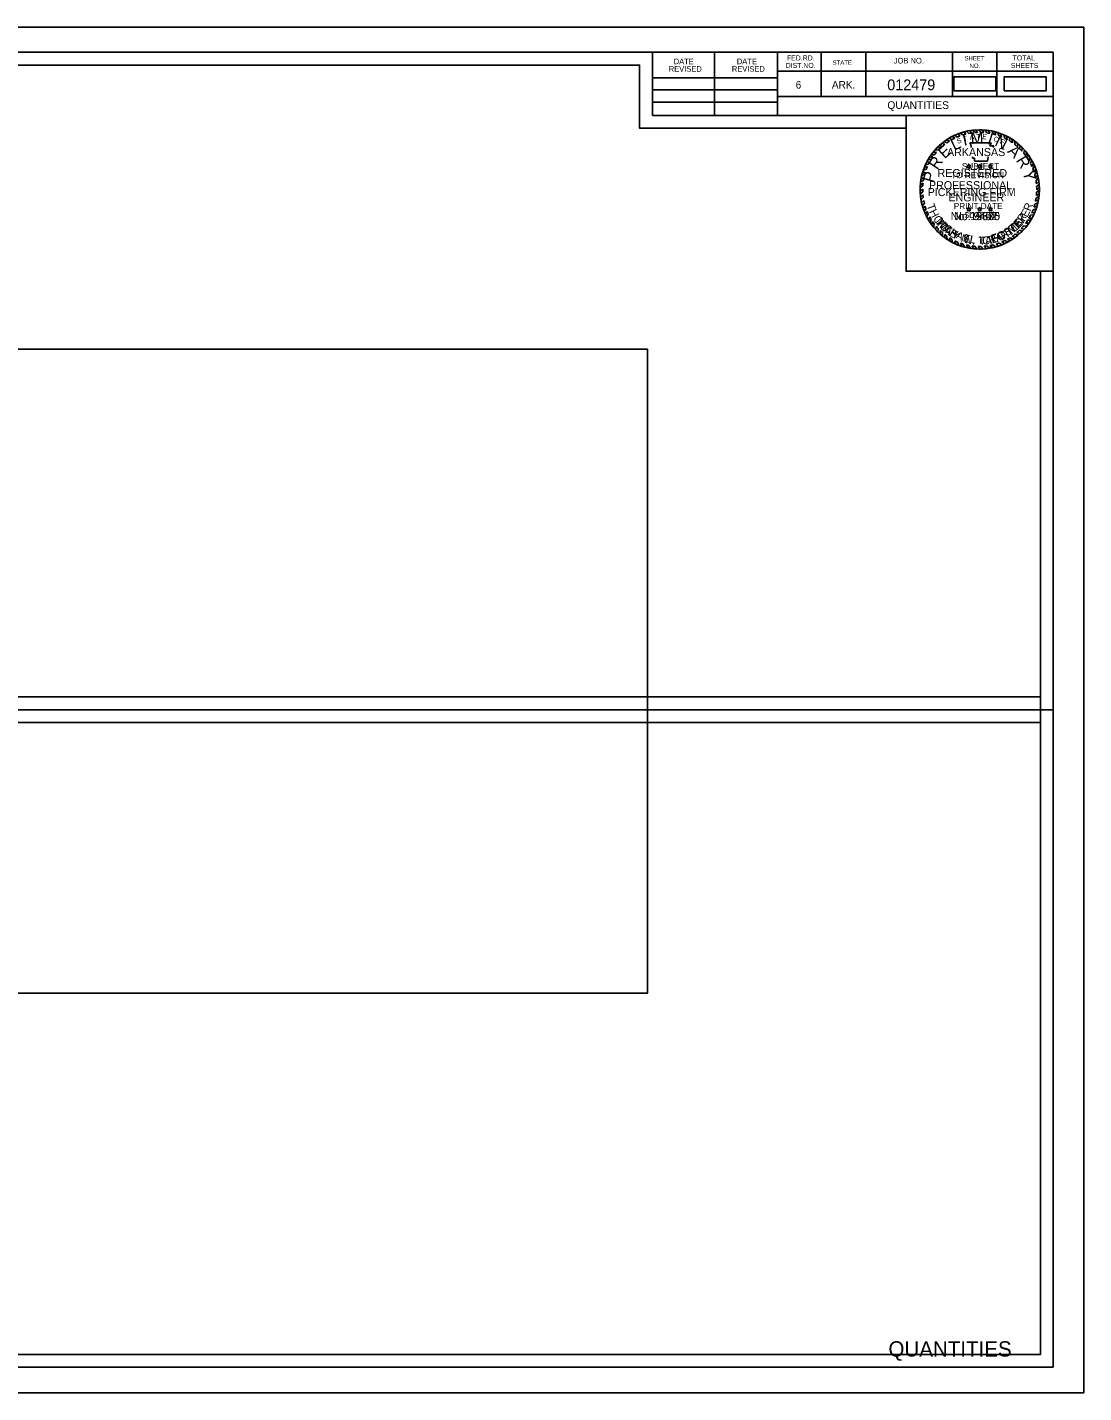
# Model space of a CAD drawing. Extents: x 1369290 to 1371547, y 379683 to 379897.
# Drawn here: x 1369458.1 to 1369623.1, y 379683.5 to 379896.8 of the extents above; entities that cross this region are included whole.
import ezdxf

# ---------------------------------------------------------------- set-up
doc = ezdxf.new("R2010")
doc.units = 0
for name, color, linetype in [('Default', 7, 'Continuous'), ('R_Border', 7, 'Continuous'), ('R_Border Notes', 7, 'Continuous'), ('R_Border Plan-Plan', 7, 'Continuous'), ('R_Border Title', 7, 'Continuous'), ('R_No Plot', 7, 'Continuous'), ('STAMP_PE_CRAFTON', 7, 'Continuous'), ('STAMP_PE_FOSTER', 7, 'Continuous'), ('STAMP_PE_SEAL-INFO', 7, 'Continuous'), ('STAMP_PE_TAEGTMEYER', 7, 'Continuous'), ('STAMP_PE_TXT', 7, 'Continuous'), ('STAMP_PRELIMINARY', 7, 'Continuous')]:
    doc.layers.add(name, color=color, linetype=linetype)

msp = doc.modelspace()

# ---------------------------------------------------------------- linework, layer by layer
at = {"layer": 'Default'}
for points in [[(1369602.84, 379886.89), (1369609.41, 379886.89), (1369609.41, 379889.08), (1369602.84, 379889.08)], [(1369610.71, 379886.89), (1369617.28, 379886.89), (1369617.28, 379889.08), (1369610.71, 379889.08)], [(1369360.05, 379745.89), (1369554.97, 379745.89), (1369554.97, 379846.52), (1369360.05, 379846.52)]]:
    msp.add_lwpolyline(points, close=True, dxfattribs=at)
at = {"layer": 'R_Border'}
for p, q in [((1369302.22, 379892.93), (1369618.4, 379892.93)), ((1369555.76, 379883.05), (1369555.76, 379892.93)), ((1369565.44, 379883.05), (1369565.44, 379892.93)), ((1369575.3, 379892.93), (1369575.3, 379883.05)), ((1369582.14, 379892.93), (1369582.14, 379885.99)), ((1369589.08, 379892.93), (1369589.08, 379885.99)), ((1369602.66, 379892.93), (1369602.66, 379885.99)), ((1369609.6, 379892.93), (1369609.6, 379885.99)), ((1369618.4, 379687.47), (1369618.4, 379892.93)), ((1369555.76, 379888.91), (1369575.3, 379888.91)), ((1369618.4, 379889.99), (1369575.3, 379889.99)), ((1369618.4, 379890.01), (1369618.4, 379890.01)), ((1369555.76, 379887.05), (1369575.3, 379887.05)), ((1369555.76, 379885.11), (1369575.3, 379885.11)), ((1369618.4, 379885.99), (1369575.3, 379885.99)), ((1369578.26, 379885.99), (1369618.4, 379885.99)), ((1369618.4, 379883.05), (1369555.76, 379883.05)), ((1369618.4, 379687.47), (1369302.22, 379687.47))]:
    msp.add_line(p, q, dxfattribs=at)
at = {"layer": 'R_Border Plan-Plan'}
msp.add_line((1369302.22, 379790.2), (1369618.4, 379790.2), dxfattribs=at)
at = {"layer": 'R_No Plot'}
for points in [[(1369289.81, 379896.82), (1369623.15, 379896.82), (1369623.15, 379683.48), (1369289.81, 379683.48)], [(1369616.4, 379792.2), (1369304.22, 379792.2), (1369304.22, 379890.93), (1369553.76, 379890.93), (1369553.76, 379881.05), (1369571.3, 379881.05), (1369595.4, 379881.05), (1369595.4, 379858.71), (1369616.4, 379858.71)], [(1369304.22, 379890.93), (1369553.76, 379890.93), (1369553.76, 379881.05), (1369571.3, 379881.05), (1369595.4, 379881.05), (1369595.4, 379858.71), (1369616.4, 379858.71), (1369616.4, 379689.47), (1369304.22, 379689.47)], [(1369595.4, 379883.05), (1369618.4, 379883.05), (1369618.4, 379858.71), (1369595.4, 379858.71)], [(1369304.22, 379788.2), (1369616.4, 379788.2), (1369616.4, 379689.47), (1369304.22, 379689.47)]]:
    msp.add_lwpolyline(points, close=True, dxfattribs=at)
at = {"layer": 'STAMP_PE_SEAL-INFO'}
for p, q in [((1369602.57, 379879.75), (1369603.03, 379879.52)), ((1369603, 379879.96), (1369603.39, 379879.68)), ((1369603.51, 379880.18), (1369603.8, 379879.85)), ((1369603.86, 379880.3), (1369604.24, 379880)), ((1369604.45, 379880.49), (1369604.74, 379880.14)), ((1369604.83, 379880.58), (1369605.19, 379880.24)), ((1369605.32, 379880.68), (1369605.62, 379880.31)), ((1369605.83, 379880.75), (1369606.11, 379880.37)), ((1369606.57, 379880.4), (1369606.26, 379880.79)), ((1369607.07, 379880.4), (1369606.79, 379880.81)), ((1369607.52, 379880.38), (1369607.27, 379880.81)), ((1369608.03, 379880.33), (1369607.74, 379880.77)), ((1369608.46, 379880.27), (1369608.2, 379880.72)), ((1369609.02, 379880.15), (1369608.84, 379880.61)), ((1369609.42, 379880.04), (1369609.26, 379880.51)), ((1369609.87, 379879.89), (1369609.73, 379880.37)), ((1369610.29, 379879.73), (1369610.15, 379880.23)), ((1369610.75, 379879.53), (1369610.65, 379880.02)), ((1369611.2, 379879.3), (1369611.11, 379879.81)), ((1369599.94, 379877.69), (1369600.46, 379877.65)), ((1369600.26, 379878.04), (1369600.8, 379877.99)), ((1369600.59, 379878.36), (1369601.05, 379878.22)), ((1369600.94, 379878.66), (1369601.47, 379878.56)), ((1369601.31, 379878.99), (1369601.77, 379878.78)), ((1369601.73, 379879.25), (1369602.18, 379879.05)), ((1369602.12, 379879.5), (1369602.55, 379879.27)), ((1369605.37, 379878.78), (1369608.71, 379878.78)), ((1369605.49, 379878.47), (1369605.37, 379878.78)), ((1369605.59, 379878.18), (1369605.49, 379878.47)), ((1369605.6, 379878.06), (1369605.59, 379878.18)), ((1369608.71, 379878.78), (1369608.49, 379878.29)), ((1369608.49, 379878.29), (1369609.12, 379878.29)), ((1369609.12, 379878.29), (1369608.98, 379878.06)), ((1369611.58, 379879.07), (1369611.54, 379879.57)), ((1369612.02, 379878.78), (1369611.99, 379879.3)), ((1369612.38, 379878.52), (1369612.41, 379879)), ((1369612.83, 379878.15), (1369612.85, 379878.67)), ((1369613.14, 379877.85), (1369613.21, 379878.35)), ((1369613.5, 379877.48), (1369613.56, 379878.01)), ((1369613.77, 379877.16), (1369613.91, 379877.63)), ((1369598.41, 379875.35), (1369598.91, 379875.46)), ((1369598.6, 379875.74), (1369599.1, 379875.81)), ((1369598.83, 379876.17), (1369599.32, 379876.19)), ((1369599.08, 379876.57), (1369599.59, 379876.6)), ((1369599.31, 379876.91), (1369599.82, 379876.91)), ((1369599.59, 379877.28), (1369600.14, 379877.3)), ((1369605.79, 379876.35), (1369605.77, 379876.57)), ((1369606.11, 379876.35), (1369605.79, 379876.35)), ((1369606.11, 379875.92), (1369606.11, 379876.35)), ((1369608.14, 379875.92), (1369606.11, 379875.92)), ((1369608.15, 379876.26), (1369608.14, 379875.92)), ((1369608.23, 379876.57), (1369608.15, 379876.26)), ((1369614.1, 379876.75), (1369614.23, 379877.25)), ((1369614.32, 379876.43), (1369614.49, 379876.89)), ((1369614.62, 379875.93), (1369614.81, 379876.42)), ((1369614.82, 379875.57), (1369615.05, 379876.01)), ((1369615.05, 379875.08), (1369615.28, 379875.57)), ((1369598.18, 379873.36), (1369597.72, 379873.11)), ((1369597.82, 379873.6), (1369598.29, 379873.8)), ((1369597.92, 379874.01), (1369598.4, 379874.18)), ((1369598.08, 379874.51), (1369598.56, 379874.65)), ((1369598.23, 379874.92), (1369598.73, 379875.07)), ((1369615.19, 379874.75), (1369615.46, 379875.18)), ((1369615.39, 379874.2), (1369615.66, 379874.67)), ((1369615.5, 379873.83), (1369615.79, 379874.28)), ((1369615.63, 379873.27), (1369615.95, 379873.72)), ((1369615.7, 379872.89), (1369616.05, 379873.25)), ((1369598, 379872.04), (1369597.58, 379871.78)), ((1369597.98, 379871.55), (1369597.58, 379871.21)), ((1369598.04, 379872.46), (1369597.6, 379872.18)), ((1369597.99, 379871.14), (1369597.6, 379870.81)), ((1369598.1, 379872.9), (1369597.65, 379872.68)), ((1369615.77, 379872.38), (1369616.14, 379872.72)), ((1369615.8, 379871.97), (1369616.19, 379872.26)), ((1369615.8, 379871.04), (1369616.22, 379871.32)), ((1369615.81, 379871.45), (1369616.22, 379871.77)), ((1369598.02, 379870.64), (1369597.65, 379870.29)), ((1369598.08, 379870.21), (1369597.72, 379869.84)), ((1369598.15, 379869.75), (1369597.81, 379869.39)), ((1369598.25, 379869.34), (1369597.94, 379868.92)), ((1369615.51, 379869.2), (1369615.98, 379869.4)), ((1369615.62, 379869.65), (1369616.07, 379869.84)), ((1369615.71, 379870.15), (1369616.15, 379870.37)), ((1369615.76, 379870.54), (1369616.19, 379870.79)), ((1369598.37, 379868.89), (1369598.08, 379868.47)), ((1369598.51, 379868.47), (1369598.23, 379868.05)), ((1369598.68, 379868.04), (1369598.42, 379867.62)), ((1369598.85, 379867.66), (1369598.62, 379867.19)), ((1369599.08, 379867.2), (1369598.89, 379866.71)), ((1369614.58, 379866.97), (1369615.08, 379867.03)), ((1369614.85, 379867.47), (1369615.34, 379867.54)), ((1369615.01, 379867.81), (1369615.5, 379867.9)), ((1369615.23, 379868.32), (1369615.71, 379868.45)), ((1369615.36, 379868.7), (1369615.85, 379868.9)), ((1369599.32, 379866.79), (1369599.14, 379866.32)), ((1369599.52, 379866.48), (1369599.41, 379865.93)), ((1369599.8, 379866.09), (1369599.7, 379865.56)), ((1369600.11, 379865.71), (1369600.02, 379865.19)), ((1369600.41, 379865.38), (1369600.35, 379864.85)), ((1369600.73, 379865.05), (1369600.7, 379864.52)), ((1369601.08, 379864.74), (1369601.07, 379864.21)), ((1369612.72, 379864.74), (1369613.19, 379864.61)), ((1369613.12, 379865.11), (1369613.56, 379864.97)), ((1369613.38, 379865.37), (1369613.86, 379865.29)), ((1369613.76, 379865.8), (1369614.22, 379865.73)), ((1369614.07, 379866.2), (1369614.57, 379866.2)), ((1369614.41, 379866.69), (1369614.89, 379866.69)), ((1369601.44, 379864.44), (1369601.46, 379863.92)), ((1369601.78, 379864.19), (1369601.81, 379863.68)), ((1369602.2, 379863.91), (1369602.26, 379863.4)), ((1369602.55, 379863.71), (1369602.64, 379863.19)), ((1369603.03, 379863.46), (1369603.19, 379862.94)), ((1369603.41, 379863.29), (1369603.58, 379862.78)), ((1369603.9, 379863.1), (1369604.11, 379862.59)), ((1369604.31, 379862.96), (1369604.53, 379862.47)), ((1369604.82, 379862.82), (1369605.03, 379862.36)), ((1369605.21, 379862.74), (1369605.46, 379862.28)), ((1369605.71, 379862.66), (1369605.95, 379862.21)), ((1369606.15, 379862.61), (1369606.43, 379862.18)), ((1369606.64, 379862.58), (1369606.94, 379862.17)), ((1369607.1, 379862.58), (1369607.44, 379862.18)), ((1369607.61, 379862.61), (1369607.94, 379862.23)), ((1369608.05, 379862.65), (1369608.43, 379862.29)), ((1369608.5, 379862.72), (1369608.89, 379862.38)), ((1369608.99, 379862.83), (1369609.37, 379862.5)), ((1369609.45, 379862.95), (1369609.87, 379862.65)), ((1369609.94, 379863.11), (1369610.39, 379862.84)), ((1369610.36, 379863.28), (1369610.78, 379863.02)), ((1369610.82, 379863.49), (1369611.3, 379863.28)), ((1369611.23, 379863.7), (1369611.65, 379863.47)), ((1369611.64, 379863.95), (1369612.09, 379863.75)), ((1369611.99, 379864.17), (1369612.43, 379863.98)), ((1369612.45, 379864.52), (1369612.92, 379864.37))]:
    msp.add_line(p, q, dxfattribs=at)
for radius, start, end in [(9.32, 117.6544, 120.8099), (9.32, 111.3124, 114.7026), (8.91, 110.3086, 113.1659), (9.32, 105.2339, 109.0352), (8.91, 104.0352, 107.3615), (9.32, 99.7525, 102.7765), (8.91, 98.258, 101.0329), (9.32, 93.9381, 96.5517), (8.91, 92.1102, 95.0367), (9.32, 87.7298, 90.6707), (8.91, 85.9628, 88.9097), (9.32, 81.9732, 84.8236), (8.91, 79.9264, 82.696), (9.32, 75.3125, 77.9426), (8.91, 73.5575, 76.2314), (9.32, 69.6061, 72.3058), (8.91, 67.6248, 70.504), (9.32, 63.1329, 66.2704), (9.32, 135.4021, 138.3031), (8.91, 133.1331, 136.2562), (9.32, 129.7326, 132.5376), (8.91, 127.5297, 130.9683), (9.32, 123.6199, 126.5906), (8.91, 121.9746, 125.11), (8.91, 115.6869, 119.1583), (8.91, 61.1558, 64.3784), (9.32, 56.9003, 60.0942), (8.91, 54.9238, 58.2702), (8.91, 48.3016, 52.0395), (9.32, 50.3492, 53.7159), (8.91, 42.2212, 45.5512), (9.32, 44.3405, 47.3929), (9.32, 38.1247, 41.2316), (9.32, 152.864, 155.5189), (9.32, 147.0072, 149.899), (8.91, 151.0315, 153.573), (9.32, 141.6056, 144.4486), (8.91, 145.0197, 148.2104), (8.91, 139.301, 142.5873), (8.91, 36.135, 39.5311), (8.91, 29.9032, 33.6645), (9.32, 31.9614, 35.4294), (8.91, 23.7732, 27.2211), (9.32, 25.9391, 29.0125), (9.32, 164.3068, 166.894), (9.32, 158.4077, 161.0701), (8.91, 167.9048, 170.9039), (8.91, 162.4331, 165.0013), (8.91, 156.3402, 159.2319), (8.91, 17.6802, 21.4251), (9.32, 19.9538, 23.3141), (8.91, 11.5444, 15.2364), (9.32, 13.8421, 17.4447), (9.32, 7.5852, 10.8621), (9.32, 175.7409, 178.2066), (9.32, 181.7251, 184.1626), (9.32, 170.0003, 172.6878), (8.91, 179.6454, 182.2633), (8.91, 173.73, 176.4734), (8.91, 5.7599, 9.0606), (8.91, 359.7329, 3.0639), (9.32, 1.7215, 4.7268), (9.32, 355.7156, 358.9569), (9.32, 187.4204, 190.1927), (9.32, 193.0369, 195.9973), (8.91, 185.4539, 188.234), (8.91, 191.2274, 193.9858), (8.91, 341.777, 345.0925), (8.91, 348.0778, 351.3435), (8.91, 353.8632, 357.1274), (9.32, 343.8925, 347.035), (9.32, 349.8305, 353.0885), (9.32, 198.8967, 201.6281), (8.91, 196.9675, 199.8353), (9.32, 204.5479, 207.4328), (8.91, 202.7761, 205.4791), (8.91, 208.7883, 211.7934), (8.91, 329.5549, 333.2076), (8.91, 335.6038, 339.1858), (9.32, 331.4037, 334.9332), (9.32, 337.3837, 340.9933), (9.32, 210.8636, 213.6571), (9.32, 216.6115, 219.491), (8.91, 214.1838, 217.2747), (9.32, 222.48, 225.3801), (8.91, 220.3909, 223.3056), (8.91, 226.2494, 229.2407), (8.91, 310.7744, 314.3161), (9.32, 312.4518, 315.6633), (8.91, 316.6531, 320.3711), (9.32, 318.2846, 321.8043), (8.91, 323.5851, 327.4407), (9.32, 325.4405, 328.9872), (9.32, 228.3665, 231.348), (8.91, 232.229, 234.9336), (9.32, 234.295, 236.9452), (8.91, 238.2223, 240.8353), (9.32, 240.1977, 242.8613), (8.91, 244.3204, 246.9486), (9.32, 246.576, 249.1558), (8.91, 250.3491, 253.1216), (9.32, 252.5967, 255.3252), (8.91, 256.505, 259.1192), (8.91, 262.3783, 265.2012), (8.91, 268.3215, 271.277), (8.91, 274.6157, 277.4486), (8.91, 280.3459, 283.5814), (8.91, 286.6423, 289.9783), (9.32, 288.5709, 291.9733), (8.91, 292.8745, 296.1185), (9.32, 294.6481, 298.2166), (8.91, 299.0768, 302.1724), (9.32, 300.621, 303.8703), (8.91, 304.823, 308.5143), (9.32, 306.3721, 310.208), (9.32, 258.4433, 261.1398), (9.32, 264.1978, 267.1009), (9.32, 270.2548, 273.3361), (9.32, 276.4239, 279.4357), (9.32, 282.3199, 285.3702)]:
    msp.add_arc((1369606.9, 379871.49), radius, start, end, dxfattribs=at)
at = {"layer": 'STAMP_PE_TXT'}
for p, q in [((1369605.12, 379875.21), (1369605.2, 379875.44)), ((1369605.2, 379875.44), (1369605.27, 379875.21)), ((1369606.82, 379875.21), (1369606.9, 379875.44)), ((1369606.9, 379875.44), (1369606.97, 379875.21)), ((1369608.52, 379875.21), (1369608.59, 379875.44)), ((1369608.59, 379875.44), (1369608.67, 379875.21)), ((1369605.08, 379875.06), (1369604.88, 379875.21)), ((1369604.88, 379875.21), (1369605.12, 379875.21)), ((1369605, 379874.83), (1369605.08, 379875.06)), ((1369605.2, 379874.97), (1369605, 379874.83)), ((1369605.4, 379874.83), (1369605.2, 379874.97)), ((1369605.27, 379875.21), (1369605.52, 379875.21)), ((1369605.52, 379875.21), (1369605.32, 379875.06)), ((1369605.32, 379875.06), (1369605.4, 379874.83)), ((1369606.77, 379875.06), (1369606.58, 379875.21)), ((1369606.58, 379875.21), (1369606.82, 379875.21)), ((1369606.7, 379874.83), (1369606.77, 379875.06)), ((1369606.9, 379874.97), (1369606.7, 379874.83)), ((1369607.1, 379874.83), (1369606.9, 379874.97)), ((1369606.97, 379875.21), (1369607.22, 379875.21)), ((1369607.22, 379875.21), (1369607.02, 379875.06)), ((1369607.02, 379875.06), (1369607.1, 379874.83)), ((1369608.47, 379875.06), (1369608.27, 379875.21)), ((1369608.27, 379875.21), (1369608.52, 379875.21)), ((1369608.4, 379874.83), (1369608.47, 379875.06)), ((1369608.59, 379874.97), (1369608.4, 379874.83)), ((1369608.79, 379874.83), (1369608.59, 379874.97)), ((1369608.67, 379875.21), (1369608.92, 379875.21)), ((1369608.92, 379875.21), (1369608.72, 379875.06)), ((1369608.72, 379875.06), (1369608.79, 379874.83)), ((1369605.08, 379868.35), (1369604.88, 379868.5)), ((1369604.88, 379868.5), (1369605.12, 379868.5)), ((1369605, 379868.12), (1369605.08, 379868.35)), ((1369605.2, 379868.27), (1369605, 379868.12)), ((1369605.12, 379868.5), (1369605.2, 379868.73)), ((1369605.2, 379868.73), (1369605.27, 379868.5)), ((1369605.4, 379868.12), (1369605.2, 379868.27)), ((1369605.27, 379868.5), (1369605.52, 379868.5)), ((1369605.52, 379868.5), (1369605.32, 379868.35)), ((1369605.32, 379868.35), (1369605.4, 379868.12)), ((1369606.77, 379868.35), (1369606.58, 379868.5)), ((1369606.58, 379868.5), (1369606.82, 379868.5)), ((1369606.7, 379868.12), (1369606.77, 379868.35)), ((1369606.9, 379868.27), (1369606.7, 379868.12)), ((1369606.82, 379868.5), (1369606.9, 379868.73)), ((1369606.9, 379868.73), (1369606.97, 379868.5)), ((1369607.1, 379868.12), (1369606.9, 379868.27)), ((1369606.97, 379868.5), (1369607.22, 379868.5)), ((1369607.22, 379868.5), (1369607.02, 379868.35)), ((1369607.02, 379868.35), (1369607.1, 379868.12)), ((1369608.47, 379868.35), (1369608.27, 379868.5)), ((1369608.27, 379868.5), (1369608.52, 379868.5)), ((1369608.4, 379868.12), (1369608.47, 379868.35)), ((1369608.59, 379868.27), (1369608.4, 379868.12)), ((1369608.52, 379868.5), (1369608.59, 379868.73)), ((1369608.59, 379868.73), (1369608.67, 379868.5)), ((1369608.79, 379868.12), (1369608.59, 379868.27)), ((1369608.67, 379868.5), (1369608.92, 379868.5)), ((1369608.92, 379868.5), (1369608.72, 379868.35)), ((1369608.72, 379868.35), (1369608.79, 379868.12))]:
    msp.add_line(p, q, dxfattribs=at)
at = {"layer": 'STAMP_PRELIMINARY'}
msp.add_circle((1369606.9, 379871.49), 9.32, dxfattribs=at)

# ---------------------------------------------------------------- texts
at = {"layer": 'R_Border'}
for s, height, p in [('FED.RD.', 0.782, (1369576.78, 379891.65)), ('TOTAL', 0.782, (1369612.04, 379891.65)), ('REVISED', 0.879, (1369558.31, 379889.88)), ('DATE', 0.879, (1369559.09, 379891.06)), ('REVISED', 0.879, (1369568.17, 379889.88)), ('DATE', 0.879, (1369568.95, 379891.06)), ('DIST.NO.', 0.782, (1369576.58, 379890.47)), ('STATE', 0.684, (1369583.9, 379890.97)), ('JOB NO.', 0.879, (1369593.48, 379891.17)), ('SHEET', 0.684, (1369604.52, 379891.65)), ('NO.', 0.684, (1369605.3, 379890.47)), ('SHEETS', 0.782, (1369611.76, 379890.47)), ('6', 1.17, (1369578.14, 379887.25)), ('ARK.', 1.172, (1369583.8, 379887.25))]:
    msp.add_text(s, height=height, dxfattribs=at).set_placement(p)
at = {"layer": 'R_Border Notes'}
for s, height, p in [('012479', 1.68, (1369592.45, 379886.99)), ('QUANTITIES', 1.2, (1369592.47, 379884.07))]:
    msp.add_text(s, height=height, dxfattribs=at).set_placement(p)
at = {"layer": 'R_Border Title'}
msp.add_text('QUANTITIES', height=2.4, dxfattribs=at).set_placement((1369592.64, 379689.12))
at = {"layer": 'STAMP_PE_CRAFTON'}
for s, rotation, p in [('T', 310.7442, (1369599.86, 379866.39)), ('N', 49.2411, (1369613.18, 379865.51)), ('O', 317.6422, (1369600.53, 379865.58)), ('N', 324.4537, (1369601.38, 379864.79)), ('Y', 331.1686, (1369602.41, 379864.08)), ('F', 28.7821, (1369610.56, 379863.62)), ('T', 34.1136, (1369611.47, 379864.13)), ('O', 41.8391, (1369612.33, 379864.73)), ('N', 347.4752, (1369604.46, 379863.16)), ('.', 356.8926, (1369605.69, 379862.88)), ('C', 6.0117, (1369607.37, 379862.83)), ('R', 14.8189, (1369608.46, 379862.95)), ('A', 20.5125, (1369609.58, 379863.25))]:
    msp.add_text(s, height=1.25, rotation=rotation, dxfattribs=at).set_placement(p)
msp.add_text('No. 12370', height=1.25, dxfattribs=at).set_placement((1369602.36, 379866.69))
at = {"layer": 'STAMP_PE_FOSTER'}
for s, rotation, p in [('M', 308.339, (1369600.01, 379866.51)), ('E', 46.9613, (1369612.9, 379865.48)), ('R', 54.5031, (1369613.62, 379866.3)), ('I', 314.1842, (1369600.81, 379865.57)), ('C', 319.8733, (1369601.16, 379865.22)), ('H', 327.7235, (1369602.09, 379864.48)), ('A', 335.7276, (1369603.07, 379863.9)), ('O', 23.719, (1369609.98, 379863.57)), ('S', 31.7234, (1369611.09, 379864.1)), ('T', 39.4194, (1369612.04, 379864.73)), ('E', 343.5779, (1369604.21, 379863.43)), ('L', 350.8115, (1369605.27, 379863.16)), ('L', 1.2666, (1369606.81, 379863)), ('.', 6.8035, (1369607.86, 379863.06)), ('F', 15.8691, (1369608.93, 379863.24))]:
    msp.add_text(s, height=1.2, rotation=rotation, dxfattribs=at).set_placement(p)
msp.add_text('No. 9402', height=1.25, dxfattribs=at).set_placement((1369602.88, 379866.69))
at = {"layer": 'STAMP_PE_TAEGTMEYER'}
for s, rotation, p in [('T', 289.646, (1369598.59, 379869)), ('R', 69.57, (1369614.84, 379868)), ('H', 296.7339, (1369598.95, 379868.02)), ('O', 303.7708, (1369599.54, 379866.91)), ('E', 46.8094, (1369612.94, 379865.27)), ('Y', 53.9986, (1369613.67, 379866.08)), ('E', 63.0984, (1369614.34, 379867.02)), ('M', 314.2033, (1369600.2, 379865.96)), ('A', 321.0594, (1369601.16, 379864.99)), ('S', 327.8239, (1369601.99, 379864.35)), ('G', 23.3052, (1369609.9, 379863.35)), ('T', 31.466, (1369611, 379863.84)), ('M', 39.3, (1369611.89, 379864.39)), ('N', 344.2727, (1369603.88, 379863.34)), ('.', 350.6464, (1369605.1, 379863.01)), ('T', 3.0061, (1369606.76, 379862.81)), ('A', 8.9826, (1369607.81, 379862.87)), ('E', 17.6836, (1369608.85, 379863.02))]:
    msp.add_text(s, height=1.25, rotation=rotation, dxfattribs=at).set_placement(p)
msp.add_text('No. 19605', height=1.25, dxfattribs=at).set_placement((1369602.36, 379866.69))
at = {"layer": 'STAMP_PE_TXT'}
for s, rotation, p in [('T', 16.311, (1369604.42, 379878.97)), ('A', 9.0679, (1369605.38, 379879.22)), ('T', 1.8248, (1369606.37, 379879.35)), ('E', 355.2002, (1369607.28, 379879.36)), ('O', 342.2506, (1369609, 379879.08)), ('S', 23.5541, (1369603.5, 379878.59)), ('F', 335.0075, (1369609.97, 379878.74))]:
    msp.add_text(s, height=0.781, rotation=rotation, dxfattribs=at).set_placement(p)
for s, p in [('ARKANSAS', (1369601.79, 379876.7)), ('REGISTERED', (1369600.31, 379873.43)), ('PROFESSIONAL', (1369598.97, 379871.53)), ('ENGINEER', (1369602.01, 379869.63))]:
    msp.add_text(s, height=1.25, dxfattribs=at).set_placement(p)
at = {"layer": 'STAMP_PRELIMINARY'}
for s, rotation, p in [('I', 12.5248, (1369604.43, 379878.28)), ('M', 3.1074, (1369605.53, 379878.59)), ('I', 342.3164, (1369608, 379878.65)), ('N', 333.9382, (1369609.11, 379878.38)), ('E', 42.3578, (1369601.42, 379876.19)), ('L', 25.513, (1369602.91, 379877.52)), ('A', 315.6579, (1369611.14, 379877.35)), ('R', 56.2292, (1369600.27, 379874.45)), ('R', 301.3831, (1369612.51, 379876.04)), ('P', 73.913, (1369599.72, 379872.43)), ('Y', 283.2593, (1369613.6, 379874.25))]:
    msp.add_text(s, height=1.8, rotation=rotation, dxfattribs=at).set_placement(p)
for s, height, p in [('SUBJECT', 0.96, (1369604.1, 379874.64)), ('TO REVISION', 0.96, (1369602.43, 379873.25)), ('PICKERING FIRM', 1.25, (1369598.77, 379870.45)), ('PRINT DATE', 0.96, (1369602.85, 379868.41)), ('$DATE$', 0.96, (1369604.53, 379867.02))]:
    msp.add_text(s, height=height, dxfattribs=at).set_placement(p)

doc.saveas('drawing.dxf')
